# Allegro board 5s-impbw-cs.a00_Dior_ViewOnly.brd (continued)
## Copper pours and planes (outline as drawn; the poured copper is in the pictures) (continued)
+1P35V_DUAL on IN2 (solid shape): outline of 3208 points within 68.99,18.38 89.38,30
+1P35V_DUAL on VCC (solid shape): outline of 411 points within 34.47,22.62 94.74,68.7
+1P35V_DUAL_BOOT_C on TOP (solid shape): 110.9,59.78 111.7,58.98 111.7,57.73 111.5,57.54 110.15,57.54 110.06,57.63 110.06,58.23 110.74,58.92 110.74,60.73 110.9,60.73
+1P35V_DUAL_BST_C on TOP (solid shape): 110.47,56.74 111.33,56.74 111.46,56.61 111.46,55.86 111.26,55.67 108.76,55.67 108.62,55.81 108.62,57.39 109.82,57.39
+1P35V_DUAL_HG_R_D on BOTTOM (solid shape): 103.23,48.6 103.22,48.6 103.22,46.9 103.3,46.82 105.64,46.82 105.72,46.74 105.72,45.41 105.44,45.13 104.79,45.13 103.96,45.96 102.71,45.96 102.55,46.12 102.55,48.77 103.07,48.77
+1P35V_DUAL_LG_R_D on BOTTOM (solid shape): 110.15,55.2 110.15,53.39 108.44,53.39 108.44,54.13 108.75,54.44 108.75,55.16 108.86,55.27 110.09,55.27
+1P35V_DUAL_PHASE_D on TOP (solid shape): 110.1,60.72 110.1,60.14 110.1,60.14 109.5,59.54 109.5,58.23 109.44,58.17 108.66,58.17 108.66,59.68 108.91,59.94 109.22,59.94 109.65,60.36 109.65,60.68 109.72,60.74 110.08,60.74
+1P35V_DUAL_PHASE_D on BOTTOM (solid shape): 108.22,54.08 108.22,51.64 107.08,51.64 106.2,50.75 106.2,49.32 105.72,48.84 105.72,47.26 105.55,47.1 103.48,47.1 103.44,47.14 103.44,48.89 103.24,49.09 102.56,49.09 102.03,49.62 102.03,51.16 101.82,51.37 101.82,51.38 100.84,52.35 100.84,54.84 101.05,55.05 107.25,55.05
+1P35V_DUAL_SN_C on BOTTOM (solid shape): 109.66,50.83 109.66,49.82 108.64,49.82 108.21,49.38 107.14,49.38 107.14,50.87 107.2,50.92 109.58,50.92
+1P35V_DUAL_VIN on BOTTOM (solid shape): 108.56,48.01 108.56,43.39 108.29,43.11 106.23,43.11 106.05,43.3 106.05,45.94 105.94,46.04 105.94,48.63 106.05,48.73 107.84,48.73
+3P3V on TOP (solid shape): 25.99,73.27 25.99,72.97 26.09,72.86 26.09,72.84 26,72.75 24.44,72.75 24.39,72.8 24.39,73.02 24.77,73.4 25.86,73.4
+3P3V on TOP (solid shape): 162.64,54.63 162.64,54.2 162.66,54.17 162.87,54.17 162.89,54.2 162.89,54.65 162.92,54.68 163.27,54.68 163.3,54.65 163.3,54.04 163.06,53.8 163.06,52.25 162.87,52.06 162.41,52.06 162.26,52.21 162.26,54.63 162.31,54.68 162.59,54.68
+3P3V on TOP (solid shape): 156.82,59.2 156.82,57.57 157.02,57.37 157.02,56.58 157,56.56 156.8,56.56 156.77,56.58 156.77,57.12 156.74,57.14 156.57,57.14 156.52,57.09 156.52,56.58 156.49,56.56 156.29,56.56 156.26,56.58 156.26,57.75 155.86,58.16 155.86,59.25 156.01,59.4 156.62,59.4
+3P3V on TOP (solid shape): 156.52,54.5 156.52,53.99 156.54,53.97 156.72,53.97 156.77,54.02 156.77,54.5 156.8,54.53 156.97,54.53 157.02,54.47 157.02,53.71 157.3,53.43 157.68,53.43 157.79,53.33 157.79,52.32 157.71,52.24 157.1,52.24 156.9,52.44 156.9,53.08 156.26,53.71 156.26,54.5 156.29,54.53 156.49,54.53
+3P3V on BOTTOM (solid shape): 117.05,60.87 117.05,57.57 115.92,56.44 114.92,56.44 114.66,56.19 114.09,56.19 113.81,56.47 113.81,57.3 114.08,57.57 114.79,57.57 114.94,57.72 114.94,59.07 115.1,59.23 115.1,60.35 115.83,61.08 116.84,61.08
+3P3V on BOTTOM (solid shape): 9.11,80.85 9.11,80.63 7.19,80.63 7.16,80.6 7.16,80.4 7.19,80.36 9.12,80.36 9.12,80.12 7.19,80.12 7.16,80.08 7.16,79.9 7.2,79.86 9.12,79.86 9.12,79.63 7.21,79.63 7.01,79.44 7.01,79.25 6.97,79.21 6.64,79.21 6.53,79.32 6.53,80.79 6.61,80.87 9.09,80.87
+3P3V on VCC (solid shape): outline of 1791 points within 0.64,4.67 184.89,91.37
+3P3V_DUAL on BOTTOM (solid shape): 39.49,86.79 39.49,86.29 39.18,85.98 37.97,85.98 37.86,86.1 37.86,86.72 38.11,86.97 39.31,86.97
+3P3V_DUAL_F on BOTTOM (solid shape): 33.51,86.61 33.51,83.07 33.14,82.7 31.76,82.7 31.64,82.72 31.51,82.7 31.38,82.7 31.05,82.37 28.77,82.37 28.69,82.46 27.64,82.46 27.53,82.36 27.53,81.31 27.43,81.2 26.86,81.2 26.67,81.39 26.67,83.51 26.86,83.69 27.81,83.69 28.14,83.37 31,83.37 31.2,83.57 31.2,84.8 31.65,85.25 31.65,86.87 31.83,87.05 33.07,87.05
+3P3V_DUAL_P on BOTTOM (solid shape): 37.28,84.95 36.91,84.59 35.52,84.59 35.36,84.75 34.48,84.75 34.28,84.95 34.28,86.93 34.35,87 37.28,87
+3P3V_EDP on BOTTOM (solid shape): outline of 997 points within 156.11,16.76 170.11,29.07
+3P3V_MINI1 on BOTTOM (solid shape): 177.49,64.26 177.49,63.92 177.01,63.44 175.48,63.44 175.29,63.26 175.29,62.24 175.25,62.19 175.21,62.18 175.11,62.16 175.02,62.13 174.94,62.09 174.86,62.04 174.78,61.99 174.7,61.93 174.64,61.87 174.57,61.8 174.52,61.72 174.47,61.64 174.42,61.56 174.39,61.47 174.36,61.38 174.34,61.29 174.33,61.19 174.33,61.1 174.33,61.01 174.34,60.91 174.36,60.82 174.39,60.73 174.43,60.64 174.47,60.56 174.52,60.48 174.58,60.4 174.64,60.33 174.71,60.27 174.76,60.23 174.77,60.21 174.78,60.18 174.79,60.15 174.78,60.12 174.77,60.1 174.76,60.09 174.14,59.47 171.53,59.47 171.26,59.74 174.1,59.74 174.1,59.97 172.18,59.97 172.18,59.74 171.26,59.74 171.22,59.78 171.22,62.37 173.46,64.61 177.14,64.61
+3P3V_MINI1 on BOTTOM (solid shape): 177.78,42.79 177.78,40.9 177.77,40.89 177.75,40.75 177.77,40.62 177.78,40.61 177.78,40.56 176.99,39.77 176.99,38.7 176.76,38.47 175.83,38.47 175.5,38.8 175.49,38.8 175.24,39.06 175.24,39.97 175.53,40.26 175.54,40.26 176.21,41.43 174.91,41.77 174.43,41.77 174.28,41.91 174.07,41.95 172.42,41.95 172.39,41.98 172.39,42.21 172.42,42.23 173.86,42.23 173.89,42.26 173.89,42.44 173.86,42.46 172.44,42.46 172.39,42.51 172.39,42.69 172.44,42.74 173.89,42.74 173.92,42.77 174.02,42.77 174.6,43.35 177.22,43.35
+3P3V_MINI1 on IN2 (solid shape): outline of 728 points within 171.72,38.4 177.83,65.8
+3P3V_MSATA on BOTTOM (solid shape): 106.07,15.84 106.07,13.89 105.97,13.78 104.88,13.78 104.73,13.94 104.73,15.49 105.21,15.97 105.94,15.97
+3P3V_MSATA on BOTTOM (solid shape): 105.5,35.19 105.5,34.79 105.05,34.35 104.16,34.35 103.96,34.15 103.96,33.52 105.07,32.42 105.07,31.68 104.88,31.49 102.44,31.49 102.29,31.65 102.29,31.72 104.58,31.72 104.58,31.95 102.72,31.95 102.72,31.72 102.29,31.72 102.29,32.4 102.49,32.6 102.49,34.55 102.58,34.58 102.65,34.61 102.72,34.65 102.79,34.7 102.85,34.76 102.91,34.82 102.95,34.88 103,34.96 103.03,35.03 103.05,35.11 104.6,35.11 104.6,35.7 104.98,35.7
+3P3V_SATA on TOP (solid shape): 186.22,58.58 186.21,58.56 186.25,58.18 186.49,57.88 186.54,57.8 186.2,57.16 186.54,56.53 186.2,55.89 186.54,55.26 186.49,55.17 186.25,54.88 186.21,54.5 186.21,54.48 186.11,54.37 184.02,54.37 183.97,54.42 183.97,55.06 183.94,55.1 183.22,55.1 183.16,55.16 183.16,57.04 182.63,57.57 181.21,57.57 181.08,57.7 181.08,58.29 181.14,58.35 182.86,58.35 183.15,58.64 186.16,58.64
+3P3VSB on TOP (solid shape): 99.29,43.02 99.29,41.79 99.14,41.64 98.3,41.64 98.02,41.92 96.42,41.92 96.08,42.26 96.08,43.27 96.45,43.64 98.67,43.64
+3P3VSB on TOP (solid shape): 111.07,54.83 111.16,54.83 111.18,54.83 111.2,54.82 111.33,54.69 111.33,53.4 109.92,51.99 108.73,51.99 108.45,52.28 108.45,54.46 108.83,54.84 110.99,54.84
+3P3VSB on TOP (solid shape): 125.23,78.15 125.5,78.07 125.77,78.15 126.06,78.15 126.26,77.94 126.26,72.66 126.49,72.43 126.49,71.65 126.26,71.42 124.36,71.42 124.16,71.62 124.16,73.68 124.77,74.29 124.77,78 124.92,78.15
+3P3VSB on BOTTOM (solid shape): 99.58,43.03 99.58,42.25 98.95,41.62 96.79,41.62 96.04,42.37 96.04,43.21 96.51,43.68 98.94,43.68
+3P3VSB on VCC (solid shape): outline of 149 points within 34.88,52.93 126.37,83.41
+A/D_DOCK_IN on TOP (solid shape): 14.66,61.33 15.03,61.33 16.13,60.23 16.13,57.28 15.31,56.46 15.31,51.75 15.17,51.61 14.32,51.61 13.47,52.46 13.47,56.59 13.92,57.04 13.92,60.04 13.63,60.33 13.27,60.33 12.94,60.67 12.94,61.33 13.08,61.47 13.79,61.47 13.88,61.56 14.43,61.56
+A/D_DOCK_IN on BOTTOM (solid shape): 81.83,6.22 81.98,6.07 82.25,5.94 82.54,6.03 82.61,6.05 82.68,6.02 82.95,5.91 83.23,6.01 83.31,6.04 83.38,6 83.67,5.84 84,5.91 84,3.61 83.51,3.11 80.87,3.11 80.59,3.39 80.59,6.93 80.63,6.96 81.83,6.96
+A/D_DOCK_IN on VCC (solid shape): outline of 270 points within 0.64,0.63 83.92,16.1
+A/D_DOCK_IN on IN3 (solid shape): outline of 926 points within 1.43,11.03 15.21,61.54
+A/D_DOCK_IN_B on BOTTOM (solid shape): outline of 594 points within 69.45,2.08 81.08,10.71
+AC_BAT_IN on TOP (solid shape): 12.7,69.13 13.13,69.13 13.31,68.95 13.31,67.53 13.17,67.39 12.2,67.39 11.73,66.91 7.66,66.91 7.65,66.91 7.24,66.91 7.2,66.94 7.2,68.91 7.11,69.01 7.11,69.13 7.14,69.17 7.85,69.17 7.85,69.91 7.91,69.97 11.86,69.97
+AC_BAT_SYS on TOP (solid shape): 23.03,90.32 23.03,89.74 22.75,89.47 20.72,89.47 20.28,89.9 20.28,90.33 20.65,90.7 22.65,90.7
+AC_BAT_SYS on TOP (solid shape): 45.71,90.71 45.71,90.56 45.73,90.54 45.73,90.29 44.9,89.46 43.15,89.46 42.84,89.77 42.84,90.4 43.15,90.71 43.75,90.71 43.95,90.91 45.51,90.91
+AC_BAT_SYS on TOP (solid shape): 18.82,4.49 18.82,2.11 18.19,1.48 13.41,1.48 13.39,1.46 9.91,1.46 9.49,1.88 9.49,4.93 9.88,5.31 18,5.31
+AC_BAT_SYS on TOP (solid shape): 163.68,14.52 163.68,10.86 163.63,10.81 163.2,10.81 163.12,10.89 163.12,12.18 162.76,12.55 161.9,12.55 161.19,13.25 161.19,14.47 161.44,14.72 163.48,14.72
+AC_BAT_SYS on TOP (solid shape): 42.63,16.24 42.63,14.21 42.29,13.87 42.29,13.63 35.95,13.63 32.49,10.17 32.49,6.62 31.9,6.02 28.23,6.02 27.93,6.32 27.93,11.16 33.78,17.01 41.86,17.01
+AC_BAT_SYS on TOP (solid shape): 12.18,65.21 13.02,65.21 13.35,64.88 15.81,64.88 15.94,64.74 15.94,63.54 15.15,62.74 14.45,62.74 14.32,62.61 14,62.58 13.8,62.32 13.02,62.32 12.67,61.97 11.47,61.97 11.36,62.08 11.36,65.54 11.44,65.61 11.78,65.61
+AC_BAT_SYS on TOP (solid shape): 146.72,67.8 148.35,67.8 151.3,64.85 151.3,60.81 153.9,58.21 153.9,51.76 153.27,51.13 149.36,51.13 149.3,51.62 149.13,52.08 148.98,52.34 148.79,52.57 148.79,56.47 148.69,56.57 148.59,56.67 146.41,58.85 146.41,62.9 143.97,65.35 143.28,65.35 142.01,66.62 142.01,67.3 141.71,67.61 140,67.61 139.25,68.36 139.25,70.13 139.57,70.45 144.08,70.45
+AC_BAT_SYS on TOP (solid shape): outline of 98 points within 43.13,1.36 48.88,13.73
+AC_BAT_SYS on TOP (solid shape): outline of 115 points within 137.87,12.54 152.78,29.75
+AC_BAT_SYS on BOTTOM (solid shape): 108.83,41.48 108.83,40.75 108.76,40.69 106.14,40.69 106.04,40.79 106.04,42.35 107.96,42.35
+AC_BAT_SYS on BOTTOM (solid shape): 5.3,20.06 5.3,17.94 4.9,17.54 4.9,15.54 4,14.63 1.76,14.63 1.53,14.86 1.53,20.11 1.67,20.25 5.12,20.25
+AC_BAT_SYS on BOTTOM (solid shape): 12.39,65.04 12.39,62.51 12.28,62.39 7.28,62.39 4.99,60.1 4.09,60.1 4,60.19 4,63.12 4.02,63.13 3.98,63.17 3.98,64.82 5.2,66.04 11.39,66.04
+AC_BAT_SYS on BOTTOM (solid shape): 143.18,15.23 143.18,2.61 142.02,1.45 125.29,1.45 124.69,2.05 124.69,2.09 124.31,2.47 124.31,4.09 124.72,4.5 124.93,4.5 125.75,5.32 126.86,5.32 127.6,6.06 138.58,6.06 138.89,6.37 138.89,14.93 139.63,15.66 142.75,15.66
+AC_BAT_SYS on BOTTOM (solid shape): 149.07,66.44 146.95,64.33 145.67,64.33 144.49,65.51 142.16,65.51 141.74,65.92 141.74,67.41 141.62,67.53 137.97,67.53 137.75,67.76 137.75,68.54 137.66,68.62 137.66,69.51 137.71,69.56 137.71,70.18 137.82,70.29 139.17,70.29 139.45,70.56 144.95,70.56
+AC_BAT_SYS on BOTTOM (solid shape): 45.85,90.44 45.85,89.27 46.61,88.51 47.12,88.51 47.78,87.85 49.35,87.85 49.43,87.77 49.43,87.11 49.13,86.81 48.16,86.81 47.35,86 46.43,86 46.18,86.25 46.18,87.32 44.93,88.56 44.93,89.7 44.45,90.19 44.17,90.19 44.02,90.34 44.02,90.71 44.1,90.79 45.5,90.79
+AC_BAT_SYS on BOTTOM (solid shape): outline of 764 points within 115.84,30.82 155.45,50.41
+AC_BAT_SYS on IN1 (solid shape): 12.92,4.63 12.92,3.32 11.96,2.36 10.19,2.36 9.46,3.09 9.46,4.98 12.57,4.98
+AC_BAT_SYS on IN1 (solid shape): 47.15,2.41 47.15,1.35 43.78,1.35 43.61,1.52 43.61,2.56 43.92,2.88 46.69,2.88
+AC_BAT_SYS on IN1 (solid shape): outline of 363 points within 88.4,1.35 127.99,6.33
+AC_BAT_SYS on IN1 (solid shape): outline of 797 points within 1.38,14.59 9.98,64.63
+AC_BAT_SYS on IN2 (solid shape): 12.89,4.61 12.89,3.31 11.96,2.38 10.21,2.38 9.46,3.12 9.46,4.96 12.55,4.96
+AC_BAT_SYS on IN2 (solid shape): 47.15,2.54 47.15,1.35 43.68,1.35 43.47,1.56 43.47,2.5 43.87,2.89 46.8,2.89
+AC_BAT_SYS on IN2 (solid shape): outline of 360 points within 88.41,1.35 127.99,6.33
+AC_BAT_SYS on IN2 (solid shape): outline of 791 points within 1.38,14.59 9.98,64.62
+AC_BAT_SYS on IN3 (solid shape): 46.64,2.79 46.64,1.66 46.33,1.35 43.79,1.35 43.54,1.6 43.54,2.51 43.97,2.94 46.48,2.94
+AC_BAT_SYS on IN3 (solid shape): 21.01,90.64 21.71,90.64 21.88,90.47 21.88,90.05 21.45,89.62 19.84,89.62 19.35,90.11 19.35,90.52 19.76,90.94 20.71,90.94
+AC_BAT_SYS on IN3 (solid shape): 93.94,2.63 93.94,1.65 93.64,1.35 87.52,1.35 87.23,1.64 87.23,2.86 87.26,2.9 93.67,2.9
+AC_BAT_SYS on IN3 (solid shape): 143.11,15.56 143.11,4.94 144.58,3.47 166.65,3.47 168.73,5.55 168.73,11.14 167.51,12.36 162.31,12.36 162.09,12.52 161.82,12.51 161.79,12.5 161.11,13.17 161.11,13.94 161.88,14.7 168.73,14.7 170.51,12.92 170.51,3.52 168.48,1.49 124.66,1.49 124.16,2 124.16,4.74 124.2,4.83 124.3,4.83 124.81,4.95 124.78,5.47 124.75,5.51 125.05,5.81 135.71,5.81 137.24,7.33 137.24,14.7 138.89,16.35 142.32,16.35
+AC_BAT_SYS on IN3 (solid shape): outline of 791 points within 2.66,62.27 12.65,89.7
+AC_SN_C on TOP (solid shape): 13.01,56.39 13.01,52.52 13.72,51.81 13.72,51.1 13.75,51.07 13.75,50.32 12.55,50.32 12.39,50.48 12.39,51.28 11.68,51.99 11.68,56.46 11.81,56.59 12.81,56.59
+AC_SN_C1 on TOP (solid shape): 16.16,56.22 16.16,52.54 16.27,52.42 16.66,52.42 17.31,51.78 17.31,50.29 15.9,50.29 15.9,51.28 15.53,51.65 15.53,56.28 16.09,56.28
+ADAPTER_IN on TOP (solid shape): 11.26,56.46 11.26,51.95 11.9,51.32 11.9,50.75 11.78,50.63 8.37,50.63 7.86,51.14 5.64,51.14 5.47,51.31 5.47,51.77 5.46,51.78 5.46,52.29 5.51,52.34 5.97,52.34 6.29,52.67 6.29,53.24 6.32,53.27 6.8,53.27 7.19,53.66 7.19,54.16 6.63,54.72 6.63,56.34 6.84,56.54 11.18,56.54
+ADAPTER_IN on BOTTOM (solid shape): 16.08,56.08 16.08,55.18 15.93,55.03 9.02,55.03 8.85,54.87 8.85,53.33 9.05,53.14 15.82,53.14 16.08,52.87 16.08,52.06 15.87,51.85 8.14,51.85 7.72,52.28 7.72,55.85 8,56.13 16.02,56.13
+EXT_DC_IN on TOP (solid shape): 10.71,65.9 10.71,61.62 11.33,61 11.78,61 12.84,59.95 13.68,59.95 13.68,57.31 9.53,57.31 9.11,56.89 6.62,56.89 6.56,56.96 6.56,59.1 6.73,59.28 7.18,59.28 7.45,59.56 7.45,60.27 7.25,60.47 6.79,60.47 6.68,60.58 6.68,61.2 6.29,61.58 6.29,66.24 6.5,66.45 10.16,66.45
+VCORE on TOP (solid shape): outline of 2607 points within 4.38,28.93 32.14,51.74
+VCORE on BOTTOM (solid shape): 10.06,45.2 9.58,44.72 9.58,39.95 9.55,39.92 8.71,39.92 8.33,39.54 6.65,39.54 5.53,40.66 5.53,41.54 5.35,41.72 4.44,41.72 4.26,41.54 4.26,40.57 4.08,40.39 1.78,40.39 1.55,40.61 1.55,45.98 10.06,45.98
+VCORE on BOTTOM (solid shape): outline of 473 points within 22.21,32.31 35.63,55.43
+VCORE on IN2 (solid shape): outline of 2591 points within 11.73,31.94 32.08,54.52
+VCORE on VCC (solid shape): 17.79,55.53 17.83,55.5 17.88,55.49 19.08,55.49 19.13,55.5 19.17,55.53 19.54,55.9 20.45,55.9 20.84,55.5 20.88,55.48 20.93,55.47 22.63,55.47 24.82,53.28 24.82,51.99 24.83,51.94 24.85,51.9 25.6,51.15 25.6,35.2 24.73,34.32 24.7,34.28 24.69,34.23 24.69,33.19 24.63,33.13 24.6,33.09 24.59,33.04 24.59,32.28 24.28,31.97 24.08,31.97 24.03,31.96 23.99,31.93 23.76,31.7 23.73,31.66 23.73,31.61 23.73,30.14 23.1,29.52 23.07,29.48 23.06,29.43 23.06,27.27 22.02,27.27 21.97,27.26 21.93,27.23 21.84,27.14 20.68,27.14 20.56,27.26 20.52,27.29 20.47,27.3 15.44,27.3 15.4,27.29 15.35,27.26 15.24,27.14 9.99,27.14 9.63,27.5 9.63,32.86 9.62,32.91 9.59,32.95 9.11,33.43 9.07,33.46 9.02,33.47 6.76,33.47 4.01,36.21 4.01,45.02 5.03,46.04 10.8,46.04 10.85,46.05 10.89,46.08 11.6,46.79 11.63,46.83 11.63,46.88 11.63,55.41 16.05,55.41 16.1,55.42 16.14,55.45 16.69,56 17.32,56
+VCORE_BST1_L1_RC_D on BOTTOM (solid shape): 2.27,27.27 2.27,24.91 1.74,24.91 1.46,25.19 1.46,27.52 2.02,27.52
+VCORE_BST1_R1_RC_D on BOTTOM (solid shape): 4.29,29.46 4.29,25.05 4.09,24.85 3.38,24.85 3.26,24.97 3.26,26.16 3.8,26.69 3.8,27.63 4.1,27.94 4.1,29.46 4.1,29.47 4.28,29.47
+VCORE_BST1_RC_D on BOTTOM (solid shape): 3.89,29.46 3.89,28.16 3.57,27.84 3.57,26.8 3.43,26.66 2.93,26.66 2.91,26.68 2.91,27.46 3.07,27.63 3.07,28.17 3.7,28.79 3.7,29.44 3.74,29.48 3.87,29.48
+VCORE_IN on BOTTOM (solid shape): 6.67,29.33 6.67,23.88 5.52,22.73 5.52,21.87 4.79,21.13 2.35,21.13 1.6,21.88 1.6,22.45 1.99,22.84 2.85,22.84 3.26,23.26 3.26,24.55 4.2,24.55 4.65,25 4.65,28.19 4.5,28.33 4.5,29.45 4.52,29.46 6.54,29.46
+VCORE_SN1_C on BOTTOM (solid shape): 8.67,34.82 8.67,31.99 8.51,31.84 8.51,31.81 7.73,31.81 7.73,33.41 7.54,33.6 7.54,34.88 7.63,34.97 8.53,34.97
+VCORE_SW1_R on BOTTOM (solid shape): 4.4,39.37 4.4,38.29 4.64,38.05 7.31,38.05 8.15,37.21 8.15,35.58 7.96,35.39 7.44,35.39 7.15,35.1 7.15,32.59 6.68,32.12 4.56,32.12 4.46,32.22 4.46,34.98 3.74,35.7 2.1,35.7 1.45,36.36 1.45,39.4 1.64,39.59 4.18,39.59
+VTT_DDR on TOP (solid shape): 111.82,60.67 112.33,60.67 113.18,59.81 113.18,59.47 113.06,59.34 112.89,59.34 112.73,59.5 112.73,59.7 112.25,60.18 111.54,60.18 111.54,60.77 111.55,60.78 111.71,60.78
+VTT_DDR on TOP (solid shape): 71.72,80.51 71.72,79.8 71.51,79.58 71.21,79.58 71.01,79.78 71.01,80.04 70.7,80.35 68.44,80.35 68.28,80.51 68.28,81.04 68.38,81.15 69.3,81.15 69.42,81.27 69.42,81.7 69.53,81.81 70.42,81.81
+VTT_DDR on TOP (solid shape): outline of 137 points within 70.51,41.06 91.44,54.02
+VTT_DDR on IN2 (solid shape): outline of 233 points within 88.68,49.13 113.66,67.8
CHG_BATDRV_R_A on BOTTOM (solid shape): 136.41,68.4 137.24,68.4 137.39,68.25 137.39,67.66 137.33,67.6 135.97,67.6 135.9,67.67 135.9,68.48 135.91,68.49 136.32,68.49
CHG_BTST_D on BOTTOM (solid shape): 146.14,55.16 146.14,54.7 145.95,54.51 143.74,54.51 143.66,54.59 143.66,55.34 143.71,55.39 145.92,55.39
CHG_BTST_D on BOTTOM (solid shape): 143.8,52.15 143.8,51.46 143.58,51.24 141.61,51.24 141.61,51.54 142.2,51.54 142.62,51.97 142.88,51.97 143.24,52.33 143.61,52.33
CHG_BTST_R_D on BOTTOM (solid shape): 141.45,60.09 141.45,59.15 141.59,59.01 141.59,58.43 141.71,58.31 141.71,57.23 141.83,57.1 142.59,57.1 142.62,57.07 142.62,56.61 142.57,56.56 141.5,56.56 141.11,56.95 141.11,58.04 140.74,58.41 140.46,58.69 140.46,59.05 140.87,59.45 140.87,60.06 140.95,60.14 141.4,60.14
CHG_HIDRV_D on BOTTOM (solid shape): 144.67,64.89 144.67,64.46 144.83,64.3 144.83,63.42 144.63,63.21 143.98,63.21 143.55,63.65 143.55,64.15 143.91,64.52 143.91,65.09 144,65.18 144.38,65.18
CHG_LODRV_D1 on BOTTOM (solid shape): 144.49,61.45 144.49,59.82 144.42,59.76 143.24,59.76 143.18,59.82 143.18,60.59 143.75,61.15 143.75,61.41 143.89,61.56 144.38,61.56
CHG_PHASE_S on BOTTOM (solid shape): 141.77,65.19 142.5,65.19 142.67,65.02 143.61,65.02 143.62,65.01 143.62,64.78 143.09,64.25 143.09,63.46 143.67,62.87 144.23,62.87 144.27,62.84 144.27,61.94 144.25,61.92 141.86,61.92 141.23,61.28 141.23,60.87 140.64,60.29 140.64,59.68 140.57,59.61 139.94,59.61 138.93,60.62 138.93,65.57 139.13,65.77 139.29,65.77 139.3,65.78 141.17,65.78
CHG_REGN_D on BOTTOM (solid shape): 143.28,55.36 143.28,54.78 143.02,54.52 143.02,53.21 143.42,52.81 143.42,52.73 143.26,52.58 142.92,52.58 142.12,51.79 141.75,51.79 141.66,51.88 141.66,51.96 141.92,52.23 141.92,53.88 141.28,54.53 141.28,55.26 141.41,55.4 143.24,55.4
CHG_VCC1_D on BOTTOM (solid shape): 144,43 143.63,42.63 143.63,41.56 143,40.94 142.29,40.94 142.17,41.06 142.17,41.93 142.32,42.08 142.32,42.95 142.42,43.04 142.42,43.98 142.62,44.18 144,44.18
CHG_VCC_D on BOTTOM (solid shape): 142.35,49.8 142.35,49.44 142.55,49.24 142.91,49.24 143.13,49.02 143.13,48.31 143.13,48.3 143.13,48.11 144.01,47.23 144.01,46.28 143.98,46.24 142.57,46.24 142.36,46.46 142.36,48.65 141.63,49.39 141.63,49.96 141.71,50.04 142.11,50.04
DC_IN_ID_POGO_Q on BOTTOM (solid shape): 62.99,9.97 62.99,8.39 62.46,7.85 62.46,7.22 62.37,7.13 60.68,7.13 60.56,7.26 60.56,7.74 61.34,8.53 61.57,8.53 61.8,8.75 61.8,9.29 61.65,9.44 61.65,9.92 61.77,10.05 62.92,10.05
POGO_ID_VOL_D on BOTTOM (solid shape): 60.87,9.02 60.87,8.5 60.25,7.88 60.25,6.9 59.51,6.16 58.47,6.16 58.32,6.32 58.32,8.65 58.4,8.73 58.9,8.73 59.29,9.11 60.78,9.11
POGO_ID_VOL_G on BOTTOM (solid shape): 61.19,6.72 61.19,4.51 60.78,4.11 59.36,4.11 59.21,4.26 59.21,5.38 60.66,6.82 61.09,6.82
N190577 on TOP (solid shape): 11.97,48.74 11.02,48.74 11.02,50.2 11.97,50.2
N190717 on TOP (solid shape): 15.62,49.28 15.62,48.4 16.21,47.82 16.21,47.13 16,46.93 15.22,46.93 15.03,47.12 15.03,47.88 14.43,48.47 12.47,48.47 12.47,49.35 15.55,49.35
N456604 on TOP (solid shape): 107.93,63.75 107.93,62.63 108.21,62.35 109.68,62.35 109.73,62.3 109.73,62.15 109.7,62.12 108.28,62.12 107.98,61.82 107.98,61.66 107.82,61.51 107.39,61.51 107.37,61.54 107.37,63.7 107.44,63.77 107.9,63.77
N19785814 on TOP (solid shape): 14.57,69.86 14.57,69.8 15.01,69.36 15.71,69.36 16.12,68.95 16.12,68.4 15.94,68.22 15.94,66.05 15.83,65.94 12.33,65.94 12.27,66 12.27,66.94 12.45,67.12 13.24,67.12 13.59,67.47 13.59,69.83 13.65,69.88
N19785881 on BOTTOM (solid shape): 135.62,69.6 135.62,67.47 136.77,66.32 136.77,62.11 136.37,61.71 133.37,61.71 132.51,62.56 132.51,63.67 132.5,63.68 132.5,67.13 131.63,68 131.46,68 131.25,68.2 131.25,69.16 131.74,69.65 133.39,69.65 133.43,69.68 135.54,69.68
N21453299 on BOTTOM (solid shape): 16.21,61.34 16.21,61.22 16.41,61.02 16.99,61.02 17.06,60.95 17.06,60.45 16.98,60.37 16.23,60.37 15.67,60.92 15.67,61.41 15.83,61.57 15.99,61.57
N21453299 on BOTTOM (solid shape): 16.9,82.71 16.9,81.87 16.92,81.84 16.92,80.81 16.72,80.61 16.27,80.61 16.17,80.71 16.03,80.71 15.89,80.85 15.89,81.3 16.07,81.48 16.07,81.81 15.86,82.01 15.86,82.83 15.93,82.9 16.71,82.9
N25225282 on TOP (solid shape): 19.04,47.66 18.9,47.52 18.59,47.52 18.35,47.59 18.12,47.52 17.47,47.52 17,47.98 17.01,48.01 16.9,48.38 16.53,48.5 16.49,48.5 16.44,48.48 16.39,48.46 15.91,48.46 15.91,49.4 19.04,49.4
N27745052 on TOP (solid shape): 171.16,39.73 171.16,39.35 171.17,39.35 171.17,37.88 170.61,37.33 170.61,36.09 169.95,35.42 169.01,35.42 168.91,35.53 168.91,36.42 169.39,36.9 169.39,37.77 170.09,37.77 170.09,38.58 169.39,38.58 169.39,39.06 169.14,39.31 169.14,39.74 169.32,39.92 170.97,39.92
N27745067 on TOP (solid shape): 169.06,13.79 169.06,13.16 169.13,13.09 170.69,13.09 170.88,12.9 170.88,12.53 169.75,11.4 168.25,11.4 168.07,11.57 168.07,12.82 168.3,13.05 168.3,13.63 168.56,13.89 168.96,13.89
N29714844 on BOTTOM (solid shape): 179.6,69.92 179.6,67.58 179.53,67.51 177.9,67.51 177.53,67.14 175.99,67.14 175.87,67.25 175.87,68.37 176,68.5 176.94,68.5 177.73,69.28 177.73,70.15 177.78,70.2 179.33,70.2

Small or netless copper shapes (teardrops, artwork), in the pictures only: 2860 on TOP, 3017 on BOTTOM, 714 on IN1, 372 on IN2, 510 on IN3

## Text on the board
BOTTOM: list("[Spacing] BOTTOM" "Shape to Route Keepin" "0 MIL [DEFAULT]" "0 MIL" "0.00 MIL" "DRC ERROR CLASS/BOTTOM" "[Shape] Route Keepin/All ((9771.94 -9313.68) (17202.26 -5741.63))" "[Bottom Shape] GND ((9771.95 -9327.29) (17202.26 -5741.58))" list(9850.680000 -9313.680000) nil)@@@list("liquid_ni" "2014/02/18 09:27:27" nil "s0dcoa16607a" "5s-impbw-cs.104")@@@list("jake_ma" "2014/02/18 09:42:11" nil "s0dcoa89107" "5s-impbw-cs.104") | list("[Physical] BOTTOM" "Pad/Pad Direct Connect" "NOT_ALLOWED [(GND_20)]" "ALL_ALLOWED" "" "DRC ERROR CLASS/BOTTOM" "[SmdPin] GND (<uTiL>cId3338<uTiL>.9) (9943.59 -8125.19)" "[ThruPin] GND (<uTiL>cId3338<uTiL>.16) (9879.81 -8098.69)" list(9879.810000 -8098.690000) nil)@@@list("liquid_ni" "2014/02/18 09:28:00" nil "s0dcoa16607a" "5s-impbw-cs.104")@@@list("jake_ma" "2014/02/18 09:45:03" nil "s0dcoa89107" "5s-impbw-cs.104") | list("[Physical] BOTTOM" "Pad/Pad Direct Connect" "NOT_ALLOWED [(GND_20)]" "ALL_ALLOWED" "" "DRC ERROR CLASS/BOTTOM" "[SmdPin] GND (<uTiL>cId3338<uTiL>.9) (9943.59 -8125.19)" "[ThruPin] GND (<uTiL>cId3338<uTiL>.13) (9879.81 -8125.19)" list(9879.810000 -8125.190000) nil)@@@list("liquid_ni" "2014/02/18 09:28:02" nil "s0dcoa16607a" "5s-impbw-cs.104")@@@list("jake_ma" "2014/02/18 09:45:07" nil "s0dcoa89107" "5s-impbw-cs.104") | list("[Physical] BOTTOM" "Pad/Pad Direct Connect" "NOT_ALLOWED [(GND_20)]" "ALL_ALLOWED" "" "DRC ERROR CLASS/BOTTOM" "[SmdPin] GND (<uTiL>cId3338<uTiL>.9) (9943.59 -8125.19)" "[ThruPin] GND (<uTiL>cId3338<uTiL>.10) (9879.81 -8151.69)" list(9879.810000 -8151.690000) nil)@@@list("liquid_ni" "2014/02/18 09:28:04" nil "s0dcoa16607a" "5s-impbw-cs.104")@@@list("jake_ma" "2014/02/18 09:45:10" nil "s0dcoa89107" "5s-impbw-cs.104") | list("[Spacing] BOTTOM" "91.Shape to SMD Pin" "20 MIL [M_20]" "14.5 MIL" "5.50 MIL" "DRC ERROR CLASS/BOTTOM" "[SmdPin] +VCORE_IN (<uTiL>cId2585<uTiL>.1) (9879.0 -8487.01)" "[Bottom Shape] +AC_BAT_SYS ((9807.25 -8762.52) (9955.74 -8541.51))" list(9881.500000 -8527.010000) nil)@@@list("liquid_ni" "2014/02/18 09:27:25" nil "s0dcoa16607a" "5s-impbw-cs.104")@@@nil | list("[Physical] BOTTOM" "Pad/Pad Direct Connect" "NOT_ALLOWED [(PWR_20)]" "ALL_ALLOWED" "" "DRC ERROR CLASS/BOTTOM" "[SmdPin] +VCORE (<uTiL>cId740<uTiL>.2) (9938.42 -7694.7)" "[SmdPin] +VCORE (<uTiL>cId727<uTiL>.2) (9938.45 -7648.31)" list(9938.420000 -7694.700000) nil)@@@list("liquid_ni" "2014/02/18 09:27:50" nil "s0dcoa16607a" "5s-impbw-cs.104")@@@list("jake_ma" "2014/02/18 09:44:36" nil "s0dcoa89107" "5s-impbw-cs.104") | list("[Physical] BOTTOM" "Pad/Pad Direct Connect" "NOT_ALLOWED [(PWR_20)]" "ALL_ALLOWED" "" "DRC ERROR CLASS/BOTTOM" "[SmdPin] +VCORE_SW1_R (<uTiL>cId72<uTiL>.2) (9943.29 -7841.0)" "[SmdPin] +VCORE_SW1_R (<uTiL>cId727<uTiL>.1) (9938.45 -7886.49)" list(9943.290000 -7841.000000) nil)@@@list("liquid_ni" "2014/02/18 09:27:48" nil "s0dcoa16607a" "5s-impbw-cs.104")@@@list("jake_ma" "2014/02/18 09:44:31" nil "s0dcoa89107" "5s-impbw-cs.104") | list("[Physical] BOTTOM" "Pad/Pad Direct Connect" "NOT_ALLOWED [(GND_20)]" "ALL_ALLOWED" "" "DRC ERROR CLASS/BOTTOM" "[SmdPin] GND (<uTiL>cId3338<uTiL>.9) (9943.59 -8125.19)" "[ThruPin] GND (<uTiL>cId3338<uTiL>.17) (9943.59 -8098.69)" list(9943.590000 -8098.690000) nil)@@@list("liquid_ni" "2014/02/18 09:28:00" nil "s0dcoa16607a" "5s-impbw-cs.104")@@@list("jake_ma" "2014/02/18 09:45:02" nil "s0dcoa89107" "5s-impbw-cs.104") | list("[Physical] BOTTOM" "Pad/Pad Direct Connect" "NOT_ALLOWED [(GND_20)]" "ALL_ALLOWED" "" "DRC ERROR CLASS/BOTTOM" "[SmdPin] GND (<uTiL>cId3338<uTiL>.9) (9943.59 -8125.19)" "[ThruPin] GND (<uTiL>cId3338<uTiL>.14) (9943.59 -8125.19)" list(9943.590000 -8125.190000) nil)@@@list("liquid_ni" "2014/02/18 09:28:02" nil "s0dcoa16607a" "5s-impbw-cs.104")@@@list("jake_ma" "2014/02/18 09:45:06" nil "s0dcoa89107" "5s-impbw-cs.104") | list("[Physical] BOTTOM" "Pad/Pad Direct Connect" "NOT_ALLOWED [(GND_20)]" "ALL_ALLOWED" "" "DRC ERROR CLASS/BOTTOM" "[SmdPin] GND (<uTiL>cId3338<uTiL>.9) (9943.59 -8125.19)" "[ThruPin] GND (<uTiL>cId3338<uTiL>.11) (9943.59 -8151.69)" list(9943.590000 -8151.690000) nil)@@@list("liquid_ni" "2014/02/18 09:28:03" nil "s0dcoa16607a" "5s-impbw-cs.104")@@@list("jake_ma" "2014/02/18 09:45:09" nil "s0dcoa89107" "5s-impbw-cs.104") | list("[Spacing] BOTTOM" "94.SMD Pin to SMD Pin" "20 MIL [M_20]" "5 MIL" "15.00 MIL" "DRC ERROR CLASS/BOTTOM" "[SmdPin] +VCORE_IN (<uTiL>cId2585<uTiL>.1) (9879.0 -8487.01)" "[SmdPin] +AC_BAT_SYS (<uTiL>cId2585<uTiL>.2) (9879.0 -8567.0)" list(9959.000000 -8527.010000) nil)@@@list("liquid_ni" "2014/02/18 09:27:27" nil "s0dcoa16607a" "5s-impbw-cs.104")@@@nil | list("[Physical] BOTTOM" "Pad/Pad Direct Connect" "NOT_ALLOWED [(GND_20)]" "ALL_ALLOWED" "" "DRC ERROR CLASS/BOTTOM" "[SmdPin] GND (<uTiL>cId3338<uTiL>.9) (9943.59 -8125.19)" "[ThruPin] GND (<uTiL>cId3338<uTiL>.18) (10007.37 -8098.69)" list(10007.370000 -8098.690000) nil)@@@list("liquid_ni" "2014/02/18 09:27:59" nil "s0dcoa16607a" "5s-impbw-cs.104")@@@list("jake_ma" "2014/02/18 09:45:01" nil "s0dcoa89107" "5s-impbw-cs.104") | list("[Physical] BOTTOM" "Pad/Pad Direct Connect" "NOT_ALLOWED [(GND_20)]" "ALL_ALLOWED" "" "DRC ERROR CLASS/BOTTOM" "[SmdPin] GND (<uTiL>cId3338<uTiL>.9) (9943.59 -8125.19)" "[ThruPin] GND (<uTiL>cId3338<uTiL>.15) (10007.37 -8125.19)" list(10007.370000 -8125.190000) nil)@@@list("liquid_ni" "2014/02/18 09:28:01" nil "s0dcoa16607a" "5s-impbw-cs.104")@@@list("jake_ma" "2014/02/18 09:45:05" nil "s0dcoa89107" "5s-impbw-cs.104") | list("[Physical] BOTTOM" "Pad/Pad Direct Connect" "NOT_ALLOWED [(GND_20)]" "ALL_ALLOWED" "" "DRC ERROR CLASS/BOTTOM" "[SmdPin] GND (<uTiL>cId3338<uTiL>.9) (9943.59 -8125.19)" "[ThruPin] GND (<uTiL>cId3338<uTiL>.12) (10007.37 -8151.69)" list(10007.370000 -8151.690000) nil)@@@list("liquid_ni" "2014/02/18 09:28:03" nil "s0dcoa16607a" "5s-impbw-cs.104")@@@list("jake_ma" "2014/02/18 09:45:08" nil "s0dcoa89107" "5s-impbw-cs.104") | list("[Physical] BOTTOM" "Pad/Pad Direct Connect" "NOT_ALLOWED [(PWR_20)]" "ALL_ALLOWED" "" "DRC ERROR CLASS/BOTTOM" "[SmdPin] +VCORE_IN (<uTiL>cId1069<uTiL>.1) (9994.96 -8283.81)" "[SmdPin] +VCORE_IN (<uTiL>cId73<uTiL>.2) (10008.04 -8284.08)" list(10008.040000 -8284.080000) nil)@@@list("liquid_ni" "2014/02/18 09:27:48" nil "s0dcoa16607a" "5s-impbw-cs.104")@@@list("jake_ma" "2014/02/18 09:44:32" nil "s0dcoa89107" "5s-impbw-cs.104") | list("[Physical] BOTTOM" "Pad/Pad Direct Connect" "NOT_ALLOWED [(GND_20)]" "ALL_ALLOWED" "" "DRC ERROR CLASS/BOTTOM" "[ThruPin] GND (<uTiL>cId3339<uTiL>.37) (10258.88 -8570.16)" "[SmdPin] GND (<uTiL>cId3339<uTiL>.33) (10299.38 -8610.66)" list(10258.880000 -8570.160000) nil)@@@list("liquid_ni" "2014/02/18 09:27:54" nil "s0dcoa16607a" "5s-impbw-cs.104")@@@list("jake_ma" "2014/02/18 09:44:49" nil "s0dcoa89107" "5s-impbw-cs.104") | list("[Physical] BOTTOM" "Pad/Pad Direct Connect" "NOT_ALLOWED [(GND_20)]" "ALL_ALLOWED" "" "DRC ERROR CLASS/BOTTOM" "[SmdPin] GND (<uTiL>cId3339<uTiL>.33) (10299.38 -8610.66)" "[ThruPin] GND (<uTiL>cId3339<uTiL>.36) (10258.88 -8651.16)" list(10258.880000 -8651.160000) nil)@@@list("liquid_ni" "2014/02/18 09:27:54" nil "s0dcoa16607a" "5s-impbw-cs.104")@@@list("jake_ma" "2014/02/18 09:44:50" nil "s0dcoa89107" "5s-impbw-cs.104") | list("[Physical] BOTTOM" "Pad/Pad Direct Connect" "NOT_ALLOWED [(GND_20)]" "ALL_ALLOWED" "" "DRC ERROR CLASS/BOTTOM" "[SmdPin] GND (<uTiL>cId3339<uTiL>.33) (10299.38 -8610.66)" "[ThruPin] GND (<uTiL>cId3339<uTiL>.35) (10339.88 -8570.16)" list(10339.880000 -8570.160000) nil)@@@list("liquid_ni" "2014/02/18 09:27:55" nil "s0dcoa16607a" "5s-impbw-cs.104")@@@list("jake_ma" "2014/02/18 09:44:51" nil "s0dcoa89107" "5s-impbw-cs.104") | list("[Physical] BOTTOM" "Pad/Pad Direct Connect" "NOT_ALLOWED [(GND_20)]" "ALL_ALLOWED" "" "DRC ERROR CLASS/BOTTOM" "[SmdPin] GND (<uTiL>cId3339<uTiL>.33) (10299.38 -8610.66)" "[ThruPin] GND (<uTiL>cId3339<uTiL>.34) (10339.88 -8651.16)" list(10339.880000 -8651.160000) nil)@@@list("liquid_ni" "2014/02/18 09:27:55" nil "s0dcoa16607a" "5s-impbw-cs.104")@@@list("jake_ma" "2014/02/18 09:44:52" nil "s0dcoa89107" "5s-impbw-cs.104") | list("[Physical] BOTTOM" "Pad/Pad Direct Connect" "NOT_ALLOWED [85OHM(DP_#5/#6/5/200)]" "ALL_ALLOWED" "" "DRC ERROR CLASS/BOTTOM" "[SmdPin] H_LP4+ (<uTiL>cId2210<uTiL>.3) (11051.21 -5817.53)" "[SmdPin] H_LP4+ (<uTiL>cId2623<uTiL>.1) (11050.23 -5816.55)" list(11050.230000 -5816.550000) nil)@@@list("liquid_ni" "2014/02/18 09:27:43" nil "s0dcoa16607a" "5s-impbw-cs.104")@@@list("jake_ma" "2014/02/18 09:44:20" nil "s0dcoa89107" "5s-impbw-cs.104") | list("[Physical] BOTTOM" "Pad/Pad Direct Connect" "NOT_ALLOWED [85OHM(DP_#5/#6/5/200)]" "ALL_ALLOWED" "" "DRC ERROR CLASS/BOTTOM" "[SmdPin] H_LP4- (<uTiL>cId2210<uTiL>.1) (11051.21 -5849.03)" "[SmdPin] H_LP4- (<uTiL>cId2623<uTiL>.4) (11050.23 -5850.01)" list(11050.230000 -5850.010000) nil)@@@list("liquid_ni" "2014/02/18 09:27:44" nil "s0dcoa16607a" "5s-impbw-cs.104")@@@list("jake_ma" "2014/02/18 09:44:23" nil "s0dcoa89107" "5s-impbw-cs.104") | list("[Physical] BOTTOM" "Pad/Pad Direct Connect" "NOT_ALLOWED [85OHM(DP_#5/#6/5/200)]" "ALL_ALLOWED" "" "DRC ERROR CLASS/BOTTOM" "[SmdPin] USB_PP3 (<uTiL>cId2210<uTiL>.4) (11116.17 -5817.53)" "[SmdPin] USB_PP3 (<uTiL>cId2623<uTiL>.2) (11117.15 -5816.55)" list(11117.150000 -5816.550000) nil)@@@list("liquid_ni" "2014/02/18 09:27:44" nil "s0dcoa16607a" "5s-impbw-cs.104")@@@list("jake_ma" "2014/02/18 09:44:21" nil "s0dcoa89107" "5s-impbw-cs.104") | list("[Physical] BOTTOM" "Pad/Pad Direct Connect" "NOT_ALLOWED [85OHM(DP_#5/#6/5/200)]" "ALL_ALLOWED" "" "DRC ERROR CLASS/BOTTOM" "[SmdPin] USB_PN3 (<uTiL>cId2210<uTiL>.2) (11116.17 -5849.03)" "[SmdPin] USB_PN3 (<uTiL>cId2623<uTiL>.3) (11117.15 -5850.01)" list(11117.150000 -5850.010000) nil)@@@list("liquid_ni" "2014/02/18 09:27:45" nil "s0dcoa16607a" "5s-impbw-cs.104")@@@list("jake_ma" "2014/02/18 09:44:24" nil "s0dcoa89107" "5s-impbw-cs.104") | list("[Design] BOTTOM" "Etch turn under SMD pad" "TRUE [NONE]" "TRUE" "" "DRC ERROR CLASS/BOTTOM" "[Path] M_CHB_CLK0 ((11261.0 -7582.5) (11273.76 -7558.31))" "[SmdPin] M_CHB_CLK0 (<uTiL>cId3248<uTiL>.AN38) (11271.76 -7560.31)" list(11271.760000 -7560.310000) nil)@@@list("liquid_ni" "2014/02/18 09:29:27" nil "s0dcoa16607a" "5s-impbw-cs.104")@@@list("jake_ma" "2014/02/18 09:49:34" nil "s0dcoa89107" "5s-impbw-cs.104") | list("[Design] BOTTOM" "Etch turn under SMD pad" "TRUE [NONE]" "TRUE" "" "DRC ERROR CLASS/BOTTOM" "[Path] M_CHA_DQ46 ((11392.49 -7917.24) (11490.75 -7883.25))" "[SmdPin] M_CHA_DQ46 (<uTiL>cId3248<uTiL>.AV52) (11394.24 -7915.49)" list(11394.240000 -7915.490000) nil)@@@list("liquid_ni" "2014/02/18 09:29:27" nil "s0dcoa16607a" "5s-impbw-cs.104")@@@list("jake_ma" "2014/02/18 09:49:33" nil "s0dcoa89107" "5s-impbw-cs.104") | list("[Design] BOTTOM" "Etch turn under SMD pad" "TRUE [NONE]" "TRUE" "" "DRC ERROR CLASS/BOTTOM" "[Path] M_CHA_DQS4 ((11405.29 -8073.74) (11546.62 -8036.04))" "[SmdPin] M_CHA_DQS4 (<uTiL>cId3248<uTiL>.AW57) (11407.04 -8037.79)" list(11407.040000 -8037.790000) nil)@@@list("liquid_ni" "2014/02/18 09:29:29" nil "s0dcoa16607a" "5s-impbw-cs.104")@@@list("jake_ma" "2014/02/18 09:49:40" nil "s0dcoa89107" "5s-impbw-cs.104") | list("[Physical] BOTTOM" "Pad/Pad Direct Connect" "NOT_ALLOWED [(PWR_20)]" "ALL_ALLOWED" "" "DRC ERROR CLASS/BOTTOM" "[SmdPin] +1P35V_DUAL (<uTiL>cId3365<uTiL>.1) (13560.45 -7005.95)" "[SmdPin] +1P35V_DUAL (<uTiL>cId746<uTiL>.1) (13566.64 -6969.5)" list(13566.640000 -6969.500000) nil)@@@list("liquid_ni" "2014/02/18 09:27:49" nil "s0dcoa16607a" "5s-impbw-cs.104")@@@list("jake_ma" "2014/02/18 09:44:33" nil "s0dcoa89107" "5s-impbw-cs.104") | list("[Physical] BOTTOM" "Pad/Pad Direct Connect" "NOT_ALLOWED [(PWR_20)]" "ALL_ALLOWED" "" "DRC ERROR CLASS/BOTTOM" "[SmdPin] +1P05V (<uTiL>cId744<uTiL>.1) (13956.0 -8940.0)" "[SmdPin] +1P05V (<uTiL>cId802<uTiL>.1) (13970.43 -8939.0)" list(13956.000000 -8940.000000) nil)@@@list("liquid_ni" "2014/02/18 09:27:50" nil "s0dcoa16607a" "5s-impbw-cs.104")@@@list("jake_ma" "2014/02/18 09:44:35" nil "s0dcoa89107" "5s-impbw-cs.104") | list("[Physical] BOTTOM" "Pad/Pad Direct Connect" "NOT_ALLOWED [(PWR_20)]" "ALL_ALLOWED" "" "DRC ERROR CLASS/BOTTOM" "[SmdPin] +1P05V (<uTiL>cId1875<uTiL>.1) (14018.12 -9125.59)" "[SmdPin] +1P05V (<uTiL>cId3731<uTiL>.1) (14043.18 -9128.1)" list(14043.180000 -9128.100000) nil)@@@list("liquid_ni" "2014/02/18 09:27:49" nil "s0dcoa16607a" "5s-impbw-cs.104")@@@list("jake_ma" "2014/02/18 09:44:34" nil "s0dcoa89107" "5s-impbw-cs.104") | list("[Physical] BOTTOM" "Pad/Pad Direct Connect" "NOT_ALLOWED [(PWR_20)]" "ALL_ALLOWED" "" "DRC ERROR CLASS/BOTTOM" "[SmdPin] +3VA (<uTiL>cId737<uTiL>.2) (14509.96 -7093.52)" "[SmdPin] +3VA (<uTiL>cId751<uTiL>.1) (14475.24 -7106.27)" list(14509.960000 -7093.520000) nil)@@@list("liquid_ni" "2014/02/18 09:28:04" nil "s0dcoa16607a" "5s-impbw-cs.104")@@@list("jake_ma" "2014/02/18 09:45:11" nil "s0dcoa89107" "5s-impbw-cs.104") | list("[Physical] BOTTOM" "Pad/Pad Direct Connect" "NOT_ALLOWED [(GND_20)]" "ALL_ALLOWED" "" "DRC ERROR CLASS/BOTTOM" "[ThruPin] GND (<uTiL>cId3337<uTiL>.23) (14584.53 -6885.47)" "[SmdPin] GND (<uTiL>cId3337<uTiL>.21) (14605.03 -6864.97)" list(14584.530000 -6885.470000) nil)@@@list("liquid_ni" "2014/02/18 09:27:56" nil "s0dcoa16607a" "5s-impbw-cs.104")@@@list("jake_ma" "2014/02/18 09:44:54" nil "s0dcoa89107" "5s-impbw-cs.104") | list("[Physical] BOTTOM" "Pad/Pad Direct Connect" "NOT_ALLOWED [(GND_20)]" "ALL_ALLOWED" "" "DRC ERROR CLASS/BOTTOM" "[SmdPin] GND (<uTiL>cId3337<uTiL>.21) (14605.03 -6864.97)" "[ThruPin] GND (<uTiL>cId3337<uTiL>.22) (14625.53 -6844.47)" list(14625.530000 -6844.470000) nil)@@@list("liquid_ni" "2014/02/18 09:27:57" nil "s0dcoa16607a" "5s-impbw-cs.104")@@@list("jake_ma" "2014/02/18 09:44:55" nil "s0dcoa89107" "5s-impbw-cs.104") | list("[Physical] BOTTOM" "Pad/Pad Direct Connect" "NOT_ALLOWED [DEFAULT]" "ALL_ALLOWED" "" "DRC ERROR CLASS/BOTTOM" "[SmdPin] +VDD_BATA_PACK (<uTiL>cId649<uTiL>.2) (15001.6 -6536.75)" "[SmdPin] +VDD_BATA_PACK (<uTiL>cId76<uTiL>.2) (15009.84 -6553.0)" list(15009.840000 -6553.000000) nil)@@@list("liquid_ni" "2014/02/18 09:27:52" nil "s0dcoa16607a" "5s-impbw-cs.104")@@@list("jake_ma" "2014/02/18 09:44:40" nil "s0dcoa89107" "5s-impbw-cs.104") | list("[Physical] BOTTOM" "Pad/Pad Direct Connect" "NOT_ALLOWED [DEFAULT]" "ALL_ALLOWED" "" "DRC ERROR CLASS/BOTTOM" "[SmdPin] N19785881 (<uTiL>cId649<uTiL>.1) (15001.6 -6615.49)" "[SmdPin] N19785881 (<uTiL>cId730<uTiL>.2) (15010.54 -6598.0)" list(15010.540000 -6598.000000) nil)@@@list("liquid_ni" "2014/02/18 09:27:53" nil "s0dcoa16607a" "5s-impbw-cs.104")@@@list("jake_ma" "2014/02/18 09:44:42" nil "s0dcoa89107" "5s-impbw-cs.104") | list("[Physical] BOTTOM" "Pad/Pad Direct Connect" "NOT_ALLOWED [(PWR_20)]" "ALL_ALLOWED" "" "DRC ERROR CLASS/BOTTOM" "[SmdPin] +5VSB (<uTiL>cId739<uTiL>.2) (15051.71 -7022.4)" "[SmdPin] +5VSB (<uTiL>cId753<uTiL>.1) (15017.27 -7038.11)" list(15051.710000 -7022.400000) nil)@@@list("liquid_ni" "2014/02/18 09:27:51" nil "s0dcoa16607a" "5s-impbw-cs.104")@@@list("jake_ma" "2014/02/18 09:44:37" nil "s0dcoa89107" "5s-impbw-cs.104") | list("[Physical] BOTTOM" "Pad/Pad Direct Connect" "NOT_ALLOWED [(PWR_20)]" "ALL_ALLOWED" "" "DRC ERROR CLASS/BOTTOM" "[SmdPin] +5VSB (<uTiL>cId738<uTiL>.2) (15052.09 -7056.21)" "[SmdPin] +5VSB (<uTiL>cId753<uTiL>.1) (15017.27 -7038.11)" list(15052.090000 -7056.210000) nil)@@@list("liquid_ni" "2014/02/18 09:27:52" nil "s0dcoa16607a" "5s-impbw-cs.104")@@@list("jake_ma" "2014/02/18 09:44:39" nil "s0dcoa89107" "5s-impbw-cs.104") | list("[Physical] BOTTOM" "Pad/Pad Direct Connect" "NOT_ALLOWED [(GND_20)]" "ALL_ALLOWED" "" "DRC ERROR CLASS/BOTTOM" "[SmdPin] GND (<uTiL>cId343<uTiL>.21) (15270.0 -7335.0)" "[ThruPin] GND (<uTiL>cId343<uTiL>.23) (15239.5 -7304.5)" list(15239.500000 -7304.500000) nil)@@@list("liquid_ni" "2014/02/18 09:27:58" nil "s0dcoa16607a" "5s-impbw-cs.104")@@@list("jake_ma" "2014/02/18 09:44:57" nil "s0dcoa89107" "5s-impbw-cs.104") | list("[Physical] BOTTOM" "Pad/Pad Direct Connect" "NOT_ALLOWED [(GND_20)]" "ALL_ALLOWED" "" "DRC ERROR CLASS/BOTTOM" "[ThruPin] GND (<uTiL>cId343<uTiL>.25) (15239.5 -7365.5)" "[SmdPin] GND (<uTiL>cId343<uTiL>.21) (15270.0 -7335.0)" list(15239.500000 -7365.500000) nil)@@@list("liquid_ni" "2014/02/18 09:27:57" nil "s0dcoa16607a" "5s-impbw-cs.104")@@@list("jake_ma" "2014/02/18 09:44:56" nil "s0dcoa89107" "5s-impbw-cs.104") | list("[Physical] BOTTOM" "Pad/Pad Direct Connect" "NOT_ALLOWED [(GND_20)]" "ALL_ALLOWED" "" "DRC ERROR CLASS/BOTTOM" "[SmdPin] GND (<uTiL>cId343<uTiL>.21) (15270.0 -7335.0)" "[ThruPin] GND (<uTiL>cId343<uTiL>.22) (15300.5 -7304.5)" list(15300.500000 -7304.500000) nil)@@@list("liquid_ni" "2014/02/18 09:27:59" nil "s0dcoa16607a" "5s-impbw-cs.104")@@@list("jake_ma" "2014/02/18 09:45:00" nil "s0dcoa89107" "5s-impbw-cs.104") | list("[Physical] BOTTOM" "Pad/Pad Direct Connect" "NOT_ALLOWED [(GND_20)]" "ALL_ALLOWED" "" "DRC ERROR CLASS/BOTTOM" "[SmdPin] GND (<uTiL>cId343<uTiL>.21) (15270.0 -7335.0)" "[ThruPin] GND (<uTiL>cId343<uTiL>.24) (15300.5 -7365.5)" list(15300.500000 -7365.500000) nil)@@@list("liquid_ni" "2014/02/18 09:27:58" nil "s0dcoa16607a" "5s-impbw-cs.104")@@@list("jake_ma" "2014/02/18 09:44:59" nil "s0dcoa89107" "5s-impbw-cs.104") | list("[Physical] BOTTOM" "Pad/Pad Direct Connect" "NOT_ALLOWED [85OHM(DP_#5/#6/5/200)]" "ALL_ALLOWED" "" "DRC ERROR CLASS/BOTTOM" "[SmdPin] USBP10- (<uTiL>cId2624<uTiL>.4) (16095.39 -5945.23)" "[SmdPin] USBP10- (<uTiL>cId2211<uTiL>.4) (16096.37 -5946.21)" list(16096.370000 -5946.210000) nil)@@@list("liquid_ni" "2014/02/18 09:27:46" nil "s0dcoa16607a" "5s-impbw-cs.104")@@@list("jake_ma" "2014/02/18 09:44:26" nil "s0dcoa89107" "5s-impbw-cs.104") | list("[Physical] BOTTOM" "Pad/Pad Direct Connect" "NOT_ALLOWED [85OHM(DP_#5/#6/5/200)]" "ALL_ALLOWED" "" "DRC ERROR CLASS/BOTTOM" "[SmdPin] USB_PN2 (<uTiL>cId2624<uTiL>.3) (16095.39 -6012.15)" "[SmdPin] USB_PN2 (<uTiL>cId2211<uTiL>.3) (16096.37 -6011.17)" list(16096.370000 -6011.170000) nil)@@@list("liquid_ni" "2014/02/18 09:27:47" nil "s0dcoa16607a" "5s-impbw-cs.104")@@@list("jake_ma" "2014/02/18 09:44:28" nil "s0dcoa89107" "5s-impbw-cs.104") | list("[Physical] BOTTOM" "Pad/Pad Direct Connect" "NOT_ALLOWED [85OHM(DP_#5/#6/5/200)]" "ALL_ALLOWED" "" "DRC ERROR CLASS/BOTTOM" "[SmdPin] USBP10+ (<uTiL>cId2624<uTiL>.1) (16128.85 -5945.23)" "[SmdPin] USBP10+ (<uTiL>cId2211<uTiL>.2) (16127.87 -5946.21)" list(16127.870000 -5946.210000) nil)@@@list("liquid_ni" "2014/02/18 09:27:46" nil "s0dcoa16607a" "5s-impbw-cs.104")@@@list("jake_ma" "2014/02/18 09:44:27" nil "s0dcoa89107" "5s-impbw-cs.104") | list("[Physical] BOTTOM" "Pad/Pad Direct Connect" "NOT_ALLOWED [85OHM(DP_#5/#6/5/200)]" "ALL_ALLOWED" "" "DRC ERROR CLASS/BOTTOM" "[SmdPin] USB_PP2 (<uTiL>cId2624<uTiL>.2) (16128.85 -6012.15)" "[SmdPin] USB_PP2 (<uTiL>cId2211<uTiL>.1) (16127.87 -6011.17)" list(16127.870000 -6011.170000) nil)@@@list("liquid_ni" "2014/02/18 09:27:47" nil "s0dcoa16607a" "5s-impbw-cs.104")@@@list("jake_ma" "2014/02/18 09:44:29" nil "s0dcoa89107" "5s-impbw-cs.104") | list("[Spacing] BOTTOM" "Shape to Route Keepin" "0 MIL [DEFAULT]" "0 MIL" "0.00 MIL" "DRC ERROR CLASS/BOTTOM" "[Shape] Route Keepin/All ((9771.94 -9313.68) (17202.26 -5741.63))" "[Bottom Shape] GND ((15928.18 -6287.5) (17202.34 -5741.64))" list(17202.260000 -6287.490000) nil)@@@list("liquid_ni" "2014/02/18 09:27:26" nil "s0dcoa16607a" "5s-impbw-cs.104")@@@list("jake_ma" "2014/02/18 09:51:33" nil "s0dcoa89107" "5s-impbw-cs.104")
Ref Des/Silkscreen Bottom: CON8 | CON1 | H6510 | PU5 | U15 | CKX1 | H3 | H2 | H1 | X1 | H4 | U1 | 2 | 4 | 8 | 10 | U10 | PU8 | PU6 | X3 | PU3 | FOR SHORT CARD CLIP | H9 | U20 | FOR LONG CARD SCREW | PU4 | X2 | CONSATA | VCORE IC | CN1 | Touch control | CPU | DIMM1 | J1 | DC POGO PIN | E2 | EC | CON9 | HOME KEY | P2 | LVDS | RTC BATTERY | CON11 | CON4 | RIO | LIO | DC JACK IN | CON10 | FAN | CON7 | DIMM SLOT | Password | Setting | Keep Password | E2:2 4 | E2:8 10 | Clear Password | BATTERY | SPI ROM | CAMERA | CON6 | CONWIFI | SATA HDD | CON3 | FOR DDR3L ONLY | M2 SSD | M2 WLAN
